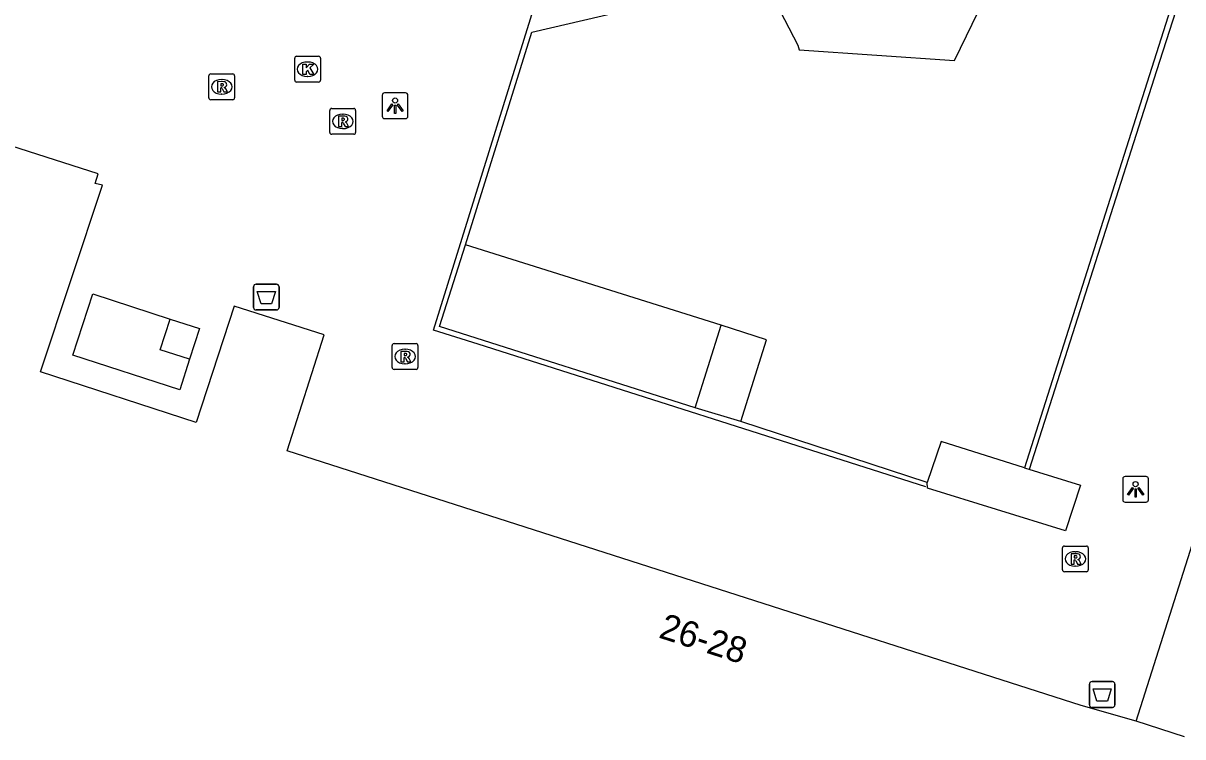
# Model space of a CAD drawing. Extents: x 160676 to 161153, y 383244 to 383713.
# Drawn here: x 161009.23 to 161054.19, y 383334.71 to 383362.39 of the extents above; entities that cross this region are included whole.
import ezdxf

# ---------------------------------------------------------------- set-up
doc = ezdxf.new("R2010")
doc.units = 0
for name, color, linetype in [('IMGEO_Afvalbak', 7, 'Continuous'), ('IMGEO_Kolk', 7, 'Continuous'), ('IMGEO_Lichtpunt', 7, 'Continuous'), ('IMGEO_Lijnafwatering', 7, 'Continuous'), ('IMGEO_Pand', 7, 'Continuous'), ('IMGEO_Pand_nummerreeks', 7, 'Continuous'), ('IMGEO_Rioolput', 7, 'Continuous'), ('IMGEO_Voetgangersgebied_open', 7, 'Continuous'), ('IMGEO_Voetpad_open', 7, 'Continuous')]:
    doc.layers.add(name, color=color, linetype=linetype)

msp = doc.modelspace()

# ---------------------------------------------------------------- linework, layer by layer
at = {"layer": 'IMGEO_Afvalbak'}
for p, q in [((161018.262, 383352.262), (161019.052, 383352.262)), ((161019.052, 383352.262), (161018.262, 383352.262)), ((161018.162, 383351.362), (161018.162, 383352.162)), ((161018.162, 383352.162), (161018.162, 383351.362)), ((161019.152, 383352.162), (161019.152, 383351.362)), ((161019.152, 383351.362), (161019.152, 383352.162)), ((161019.052, 383351.262), (161018.262, 383351.262)), ((161018.262, 383351.262), (161019.052, 383351.262)), ((161050.567, 383335.948), (161050.567, 383336.748)), ((161050.567, 383336.748), (161050.567, 383335.948)), ((161050.667, 383336.848), (161051.457, 383336.848)), ((161051.457, 383336.848), (161050.667, 383336.848)), ((161051.557, 383336.748), (161051.557, 383335.948)), ((161051.557, 383335.948), (161051.557, 383336.748)), ((161051.457, 383335.848), (161050.667, 383335.848)), ((161050.667, 383335.848), (161051.457, 383335.848))]:
    msp.add_line(p, q, dxfattribs=at)
for points in [[(161018.305, 383351.976), (161019.009, 383351.976), (161018.86, 383351.506), (161018.454, 383351.506), (161018.305, 383351.976)], [(161050.71, 383336.562), (161051.414, 383336.562), (161051.265, 383336.092), (161050.859, 383336.092), (161050.71, 383336.562)]]:
    msp.add_lwpolyline(points, dxfattribs=at)
for centre, start, end in [((161018.262, 383352.162), 90, 180), ((161018.262, 383352.162), 90, 180), ((161019.052, 383352.162), 0, 90), ((161019.052, 383352.162), 360, 90), ((161018.262, 383351.362), 180, 270), ((161018.262, 383351.362), 180, 270), ((161019.052, 383351.362), 270, 0), ((161019.052, 383351.362), 270, 0), ((161050.667, 383336.748), 90, 180), ((161050.667, 383336.748), 90, 180), ((161051.457, 383336.748), 0, 90), ((161051.457, 383336.748), 360, 90), ((161050.667, 383335.948), 180, 270), ((161050.667, 383335.948), 180, 270), ((161051.457, 383335.948), 270, 0), ((161051.457, 383335.948), 270, 0)]:
    msp.add_arc(centre, 0.1, start, end, dxfattribs=at)
at = {"layer": 'IMGEO_Kolk'}
for p, q in [((161019.759, 383360.174), (161019.759, 383361.026)), ((161019.834, 383361.1), (161020.686, 383361.1)), ((161020.247, 383360.88), (161020.272, 383360.88)), ((161020.76, 383361.026), (161020.76, 383360.174)), ((161020.686, 383360.1), (161019.834, 383360.1)), ((161020.27, 383360.32), (161020.245, 383360.32))]:
    msp.add_line(p, q, dxfattribs=at)
for points in [[(161019.759, 383360.174), (161019.759, 383361.026)], [(161019.834, 383361.1), (161020.686, 383361.1)], [(161020.08, 383360.8), (161020.203, 383360.8), (161020.203, 383360.649), (161020.333, 383360.8), (161020.497, 383360.8), (161020.351, 383360.649), (161020.504, 383360.4), (161020.352, 383360.4), (161020.267, 383360.564), (161020.203, 383360.497), (161020.203, 383360.4), (161020.08, 383360.4), (161020.08, 383360.8)], [(161020.76, 383361.026), (161020.76, 383360.174)], [(161020.686, 383360.1), (161019.834, 383360.1)]]:
    msp.add_lwpolyline(points, dxfattribs=at)
for centre, start, end in [((161019.836, 383361.024), 91.552, 178.448), ((161019.836, 383361.024), 91.552, 178.448), ((161020.684, 383361.024), 1.552, 88.448), ((161020.684, 383361.024), 1.552, 88.448), ((161019.836, 383360.176), 181.552, 268.448), ((161019.836, 383360.176), 181.552, 268.448), ((161020.684, 383360.176), 271.552, 358.448), ((161020.684, 383360.176), 271.552, 358.448)]:
    msp.add_arc(centre, 0.0765, start, end, dxfattribs=at)
for centre, major_axis, ratio, start_param, end_param in [((161020.246, 383360.6), (-0.387, 0.002), 0.722429, 4.712389, 7.853982), ((161020.271, 383360.6), (-0.39, 0.002), 0.717154, 1.570796, 4.712389)]:
    msp.add_ellipse(centre, major_axis=major_axis, ratio=ratio, start_param=start_param, end_param=end_param, dxfattribs=at)
at = {"layer": 'IMGEO_Lichtpunt'}
for p, q in [((161023.151, 383359.588), (161023.151, 383358.781)), ((161023.151, 383359.588), (161023.151, 383358.781)), ((161024.053, 383359.683), (161023.245, 383359.683)), ((161024.053, 383359.683), (161023.245, 383359.683)), ((161024.147, 383358.781), (161024.147, 383359.588)), ((161024.147, 383358.781), (161024.147, 383359.588)), ((161023.245, 383358.687), (161024.053, 383358.687)), ((161023.245, 383358.687), (161024.053, 383358.687)), ((161051.858, 383344.709), (161051.858, 383343.902)), ((161051.858, 383344.709), (161051.858, 383343.902)), ((161052.76, 383344.804), (161051.952, 383344.804)), ((161052.76, 383344.804), (161051.952, 383344.804)), ((161052.854, 383343.902), (161052.854, 383344.709)), ((161052.854, 383343.902), (161052.854, 383344.709)), ((161051.952, 383343.808), (161052.76, 383343.808)), ((161051.952, 383343.808), (161052.76, 383343.808))]:
    msp.add_line(p, q, dxfattribs=at)
for points in [[(161023.525, 383359.252), (161023.564, 383359.224), (161023.376, 383358.962), (161023.338, 383358.989), (161023.525, 383359.252)], [(161023.627, 383359.204), (161023.674, 383359.204), (161023.674, 383358.882), (161023.627, 383358.882), (161023.627, 383359.204)], [(161023.737, 383359.224), (161023.775, 383359.251), (161023.962, 383358.989), (161023.923, 383358.961), (161023.737, 383359.224)], [(161052.232, 383344.373), (161052.271, 383344.345), (161052.083, 383344.083), (161052.045, 383344.11), (161052.232, 383344.373)], [(161052.334, 383344.325), (161052.381, 383344.325), (161052.381, 383344.003), (161052.334, 383344.003), (161052.334, 383344.325)], [(161052.444, 383344.345), (161052.482, 383344.372), (161052.669, 383344.11), (161052.63, 383344.082), (161052.444, 383344.345)]]:
    msp.add_lwpolyline(points, dxfattribs=at)
for centre in [(161023.65, 383359.386), (161052.357, 383344.507)]:
    msp.add_circle(centre, 0.0994, dxfattribs=at)
for centre, start, end in [((161023.245, 383359.588), 90, 180), ((161023.245, 383359.588), 90, 180), ((161024.053, 383359.588), 0, 90), ((161024.053, 383359.588), 0, 90), ((161023.245, 383358.781), 180, 270), ((161023.245, 383358.781), 180, 270), ((161024.053, 383358.781), 270, 0), ((161024.053, 383358.781), 270, 360), ((161051.952, 383344.709), 90, 180), ((161051.952, 383344.709), 90, 180), ((161052.76, 383344.709), 0, 90), ((161052.76, 383344.709), 0, 90), ((161051.952, 383343.902), 180, 270), ((161051.952, 383343.902), 180, 270), ((161052.76, 383343.902), 270, 0), ((161052.76, 383343.902), 270, 360)]:
    msp.add_arc(centre, 0.0946, start, end, dxfattribs=at)
at = {"layer": 'IMGEO_Lijnafwatering'}
for points in [[(161026.873, 383349.932), (161025.141, 383350.484), (161030.016, 383366.136)], [(161048.242, 383345.083), (161053.185, 383360.554), (161054.421, 383364.422)], [(161044.224, 383344.398), (161026.873, 383349.932)]]:
    msp.add_lwpolyline(points, dxfattribs=at)
at = {"layer": 'IMGEO_Pand'}
for points in [[(161052.382, 383335.311), (161050.252, 383335.927), (161019.467, 383345.797), (161020.898, 383350.298), (161017.412, 383351.416), (161015.941, 383346.9), (161009.904, 383348.868), (161012.311, 383356.101), (161012.028, 383356.167), (161012.145, 383356.538), (161000, 383360.437), (160995.127, 383362.001)], [(161035.277, 383347.462), (161025.375, 383350.62), (161026.381, 383353.793)], [(161036.288, 383350.667), (161026.381, 383353.793)], [(161035.277, 383347.462), (161036.288, 383350.667)], [(161054.249, 383334.707), (161052.382, 383335.311)]]:
    msp.add_lwpolyline(points, dxfattribs=at)
at = {"layer": 'IMGEO_Rioolput'}
for p, q in [((161016.429, 383359.492), (161016.429, 383360.344)), ((161016.504, 383360.418), (161017.356, 383360.418)), ((161017.43, 383360.344), (161017.43, 383359.492)), ((161016.917, 383360.198), (161016.942, 383360.198)), ((161016.94, 383359.638), (161016.915, 383359.638)), ((161017.356, 383359.418), (161016.504, 383359.418)), ((161021.12, 383358.151), (161021.12, 383359.003)), ((161021.195, 383359.077), (161022.047, 383359.077)), ((161022.121, 383359.003), (161022.121, 383358.151)), ((161021.608, 383358.857), (161021.633, 383358.857)), ((161021.631, 383358.297), (161021.606, 383358.297)), ((161022.047, 383358.077), (161021.195, 383358.077)), ((161023.536, 383349.03), (161023.536, 383349.882)), ((161023.611, 383349.956), (161024.463, 383349.956)), ((161024.024, 383349.736), (161024.049, 383349.736)), ((161024.537, 383349.882), (161024.537, 383349.03)), ((161024.047, 383349.176), (161024.022, 383349.176)), ((161024.463, 383348.956), (161023.611, 383348.956)), ((161049.52, 383341.181), (161049.52, 383342.033)), ((161049.595, 383342.107), (161050.447, 383342.107)), ((161050.521, 383342.033), (161050.521, 383341.181)), ((161050.008, 383341.887), (161050.033, 383341.887)), ((161050.447, 383341.107), (161049.595, 383341.107)), ((161050.031, 383341.327), (161050.006, 383341.327))]:
    msp.add_line(p, q, dxfattribs=at)
for points in [[(161016.429, 383359.492), (161016.429, 383360.344)], [(161016.504, 383360.418), (161017.356, 383360.418)], [(161017.43, 383360.344), (161017.43, 383359.492)], [(161017.018, 383360.116), (161016.766, 383360.118), (161016.766, 383359.718)], [(161016.944, 383360.037), (161016.89, 383360.037), (161016.89, 383359.956)], [(161016.89, 383359.956), (161016.942, 383359.956)], [(161016.766, 383359.718), (161016.89, 383359.718), (161016.89, 383359.88), (161016.901, 383359.88)], [(161016.948, 383359.851), (161017.019, 383359.718), (161017.159, 383359.718), (161017.094, 383359.844)], [(161017.356, 383359.418), (161016.504, 383359.418)], [(161021.12, 383358.151), (161021.12, 383359.003)], [(161021.195, 383359.077), (161022.047, 383359.077)], [(161022.121, 383359.003), (161022.121, 383358.151)], [(161021.709, 383358.775), (161021.457, 383358.777), (161021.457, 383358.377)], [(161021.457, 383358.377), (161021.581, 383358.377), (161021.581, 383358.539), (161021.592, 383358.539)], [(161021.635, 383358.696), (161021.581, 383358.696), (161021.581, 383358.615)], [(161021.581, 383358.615), (161021.633, 383358.615)], [(161021.639, 383358.51), (161021.71, 383358.377), (161021.85, 383358.377), (161021.785, 383358.503)], [(161022.047, 383358.077), (161021.195, 383358.077)], [(161023.536, 383349.03), (161023.536, 383349.882)], [(161023.611, 383349.956), (161024.463, 383349.956)], [(161024.125, 383349.654), (161023.873, 383349.656), (161023.873, 383349.256)], [(161024.051, 383349.575), (161023.997, 383349.575), (161023.997, 383349.494)], [(161024.537, 383349.882), (161024.537, 383349.03)], [(161023.873, 383349.256), (161023.997, 383349.256), (161023.997, 383349.418), (161024.008, 383349.418)], [(161023.997, 383349.494), (161024.049, 383349.494)], [(161024.055, 383349.389), (161024.126, 383349.256), (161024.266, 383349.256), (161024.201, 383349.382)], [(161024.463, 383348.956), (161023.611, 383348.956)], [(161049.52, 383341.181), (161049.52, 383342.033)], [(161049.595, 383342.107), (161050.447, 383342.107)], [(161050.521, 383342.033), (161050.521, 383341.181)], [(161050.109, 383341.805), (161049.857, 383341.807), (161049.857, 383341.407)], [(161049.857, 383341.407), (161049.981, 383341.407), (161049.981, 383341.569), (161049.992, 383341.569)], [(161050.035, 383341.726), (161049.981, 383341.726), (161049.981, 383341.645)], [(161049.981, 383341.645), (161050.033, 383341.645)], [(161050.039, 383341.54), (161050.11, 383341.407), (161050.25, 383341.407), (161050.185, 383341.533)], [(161050.447, 383341.107), (161049.595, 383341.107)]]:
    msp.add_lwpolyline(points, dxfattribs=at)
for centre, radius, start, end in [((161016.506, 383360.342), 0.0765, 91.552, 178.448), ((161016.506, 383360.342), 0.0765, 91.552, 178.448), ((161017.354, 383360.342), 0.0765, 1.552, 88.448), ((161017.354, 383360.342), 0.0765, 1.552, 88.448), ((161016.926, 383360.145), 0.19, 274.7715, 282.9687), ((161016.95, 383359.941), 0.0964, 77.0061, 93.1865), ((161016.964, 383359.998), 0.0378, 276.6634, 79.6772), ((161017.017, 383360.006), 0.109, 350.3612, 89.416), ((161017.015, 383360.006), 0.112, 277.5842, 350.9817), ((161016.999, 383359.791), 0.108, 29.5134, 73.7905), ((161016.506, 383359.494), 0.0765, 181.552, 268.448), ((161016.506, 383359.494), 0.0765, 181.552, 268.448), ((161016.9, 383359.827), 0.0533, 26.0293, 88.6989), ((161017.354, 383359.494), 0.0765, 271.552, 358.448), ((161017.354, 383359.494), 0.0765, 271.552, 358.448), ((161021.197, 383359.001), 0.0765, 91.552, 178.448), ((161021.197, 383359.001), 0.0765, 91.552, 178.448), ((161022.045, 383359.001), 0.0765, 1.552, 88.448), ((161022.045, 383359.001), 0.0765, 1.552, 88.448), ((161021.591, 383358.486), 0.0533, 26.0293, 88.6989), ((161021.617, 383358.804), 0.19, 274.7715, 282.9687), ((161021.641, 383358.6), 0.0964, 77.0061, 93.1865), ((161021.655, 383358.657), 0.0378, 276.6634, 79.6772), ((161021.708, 383358.665), 0.109, 350.3612, 89.416), ((161021.706, 383358.665), 0.112, 277.5842, 350.9817), ((161021.69, 383358.45), 0.108, 29.5134, 73.7905), ((161021.197, 383358.153), 0.0765, 181.552, 268.448), ((161021.197, 383358.153), 0.0765, 181.552, 268.448), ((161022.045, 383358.153), 0.0765, 271.552, 358.448), ((161022.045, 383358.153), 0.0765, 271.552, 358.448), ((161023.613, 383349.88), 0.0765, 91.552, 178.448), ((161023.613, 383349.88), 0.0765, 91.552, 178.448), ((161024.057, 383349.479), 0.0964, 77.0061, 93.1865), ((161024.071, 383349.536), 0.0378, 276.6634, 79.6772), ((161024.124, 383349.544), 0.109, 350.3612, 89.416), ((161024.461, 383349.88), 0.0765, 1.552, 88.448), ((161024.461, 383349.88), 0.0765, 1.552, 88.448), ((161024.007, 383349.365), 0.0533, 26.0293, 88.6989), ((161024.033, 383349.683), 0.19, 274.7715, 282.9687), ((161024.122, 383349.544), 0.112, 277.5842, 350.9817), ((161024.106, 383349.329), 0.108, 29.5134, 73.7905), ((161023.613, 383349.032), 0.0765, 181.552, 268.448), ((161023.613, 383349.032), 0.0765, 181.552, 268.448), ((161024.461, 383349.032), 0.0765, 271.552, 358.448), ((161024.461, 383349.032), 0.0765, 271.552, 358.448), ((161049.597, 383342.031), 0.0765, 91.552, 178.448), ((161049.597, 383342.031), 0.0765, 91.552, 178.448), ((161050.445, 383342.031), 0.0765, 1.552, 88.448), ((161050.445, 383342.031), 0.0765, 1.552, 88.448), ((161049.991, 383341.516), 0.0533, 26.0293, 88.6989), ((161050.017, 383341.834), 0.19, 274.7715, 282.9687), ((161050.041, 383341.63), 0.0964, 77.0061, 93.1865), ((161050.055, 383341.687), 0.0378, 276.6634, 79.6772), ((161050.108, 383341.695), 0.109, 350.3612, 89.416), ((161050.106, 383341.695), 0.112, 277.5842, 350.9817), ((161050.09, 383341.48), 0.108, 29.5134, 73.7905), ((161049.597, 383341.183), 0.0765, 181.552, 268.448), ((161049.597, 383341.183), 0.0765, 181.552, 268.448), ((161050.445, 383341.183), 0.0765, 271.552, 358.448), ((161050.445, 383341.183), 0.0765, 271.552, 358.448)]:
    msp.add_arc(centre, radius, start, end, dxfattribs=at)
for centre, major_axis, ratio, start_param, end_param in [((161016.916, 383359.918), (-0.387, 0.002), 0.722429, 4.712389, 7.853982), ((161016.941, 383359.918), (-0.39, 0.002), 0.717154, 1.570796, 4.712389), ((161021.607, 383358.577), (-0.387, 0.002), 0.722429, 4.712389, 7.853982), ((161021.632, 383358.577), (-0.39, 0.002), 0.717154, 1.570796, 4.712389), ((161024.023, 383349.456), (-0.387, 0.002), 0.722429, 4.712389, 7.853982), ((161024.048, 383349.456), (-0.39, 0.002), 0.717154, 1.570796, 4.712389), ((161050.007, 383341.607), (-0.387, 0.002), 0.722429, 4.712389, 7.853982), ((161050.032, 383341.607), (-0.39, 0.002), 0.717154, 1.570796, 4.712389)]:
    msp.add_ellipse(centre, major_axis=major_axis, ratio=ratio, start_param=start_param, end_param=end_param, dxfattribs=at)
at = {"layer": 'IMGEO_Voetgangersgebied_open'}
for points in [[(161026.381, 383353.793), (161028.948, 383362.035), (161037.681, 383364.074), (161037.883, 383364.204), (161039.257, 383361.529), (161039.315, 383361.357), (161045.33, 383360.94), (161048.315, 383367.095), (161048.361, 383367.334), (161050.641, 383366.558), (161053.788, 383363.183), (161048.05, 383345.142)], [(161044.281, 383344.567), (161037.051, 383346.942)]]:
    msp.add_lwpolyline(points, dxfattribs=at)
at = {"layer": 'IMGEO_Voetpad_open'}
for points in [[(161052.382, 383335.311), (161062.237, 383366.382)], [(161015.688, 383349.349), (161015.301, 383348.161), (161011.165, 383349.508), (161011.939, 383351.885), (161014.934, 383350.91)], [(161015.688, 383349.349), (161014.547, 383349.721), (161014.934, 383350.91)], [(161014.934, 383350.91), (161016.075, 383350.538), (161015.688, 383349.349)], [(161037.051, 383346.942), (161038.054, 383350.105), (161036.288, 383350.667)], [(161037.051, 383346.942), (161035.277, 383347.462)], [(161048.05, 383345.142), (161044.816, 383346.16), (161044.281, 383344.567)], [(161048.05, 383345.142), (161050.22, 383344.47), (161049.644, 383342.702), (161044.288, 383344.349), (161044.281, 383344.567)]]:
    msp.add_lwpolyline(points, dxfattribs=at)

# ---------------------------------------------------------------- texts
at = {"layer": 'IMGEO_Pand_nummerreeks'}
msp.add_text('26-28', height=1, rotation=342.2211, dxfattribs=at).set_placement((161033.831, 383338.566))

doc.saveas('drawing.dxf')
